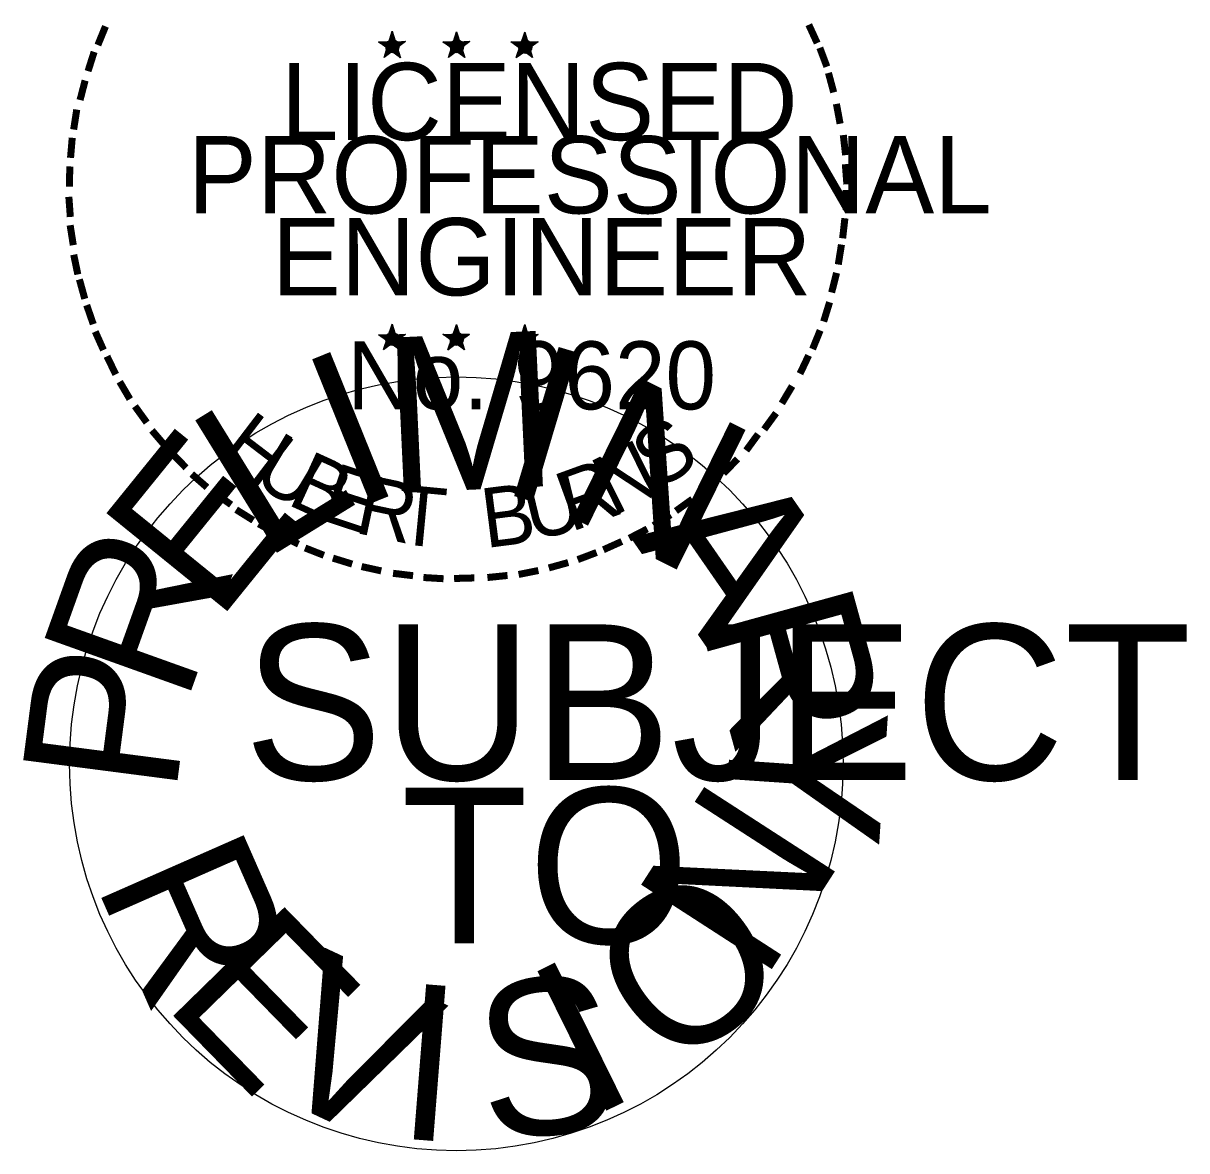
# Model space of a CAD drawing. Extents: x 6028666 to 6031787, y 5366484 to 5368484.
# Drawn here: x 6031338 to 6031786.7, y 5366523.4 to 5366958.2 of the extents above; entities that cross this region are included whole.
import ezdxf

# ---------------------------------------------------------------- set-up
doc = ezdxf.new("R2010")
doc.units = 0
doc.layers.add('Level 49', color=7, linetype='Continuous')
doc.layers.add('R_Border Prelim', color=7, linetype='Continuous')

msp = doc.modelspace()

# ---------------------------------------------------------------- linework, layer by layer
at = {"layer": 'Level 49'}
for p, q in [((6031480.22, 5366955.09), (6031479.51, 5366951.4)), ((6031480.22, 5366955.09), (6031479.52, 5366951.04)), ((6031480.22, 5366955.09), (6031479.88, 5366951.41)), ((6031480.26, 5366949.39), (6031480.22, 5366955.09)), ((6031480.22, 5366955.09), (6031481.17, 5366951.05)), ((6031480.22, 5366955.09), (6031480.98, 5366951.41)), ((6031480.22, 5366955.09), (6031480.43, 5366951.41)), ((6031505.06, 5366954.89), (6031504.35, 5366951.02)), ((6031505.06, 5366954.89), (6031504.35, 5366951.21)), ((6031505.06, 5366954.89), (6031504.53, 5366951.21)), ((6031505.09, 5366949.56), (6031505.06, 5366954.89)), ((6031505.06, 5366954.89), (6031506, 5366951.04)), ((6031505.06, 5366954.89), (6031505.82, 5366951.22)), ((6031505.06, 5366954.89), (6031505.27, 5366951.22)), ((6031531.36, 5366954.71), (6031530.47, 5366951.21)), ((6031531.36, 5366954.71), (6031531.02, 5366951.03)), ((6031531.36, 5366954.71), (6031531.02, 5366951.03)), ((6031531.4, 5366949.19), (6031531.36, 5366954.71)), ((6031531.36, 5366954.71), (6031532.49, 5366951.04)), ((6031531.36, 5366954.71), (6031532.12, 5366951.03)), ((6031531.36, 5366954.71), (6031531.76, 5366951.03)), ((6031474.92, 5366951), (6031480.26, 5366949.39)), ((6031474.92, 5366951), (6031478.78, 5366950.85)), ((6031474.92, 5366951), (6031478.78, 5366950.66)), ((6031474.92, 5366951), (6031478.42, 5366950.11)), ((6031474.92, 5366951), (6031478.42, 5366949.56)), ((6031474.92, 5366951), (6031478.42, 5366949.37)), ((6031474.92, 5366951), (6031478.43, 5366948.82)), ((6031477.17, 5366944.95), (6031480.26, 5366949.39)), ((6031485.4, 5366951.08), (6031480.26, 5366949.39)), ((6031483.42, 5366944.81), (6031480.26, 5366949.39)), ((6031485.4, 5366951.08), (6031480.62, 5366950.68)), ((6031485.4, 5366951.08), (6031481.18, 5366950.31)), ((6031485.4, 5366951.08), (6031481.18, 5366949.94)), ((6031483.42, 5366944.81), (6031481.73, 5366949.4)), ((6031485.4, 5366951.08), (6031481.91, 5366949.95)), ((6031485.4, 5366951.08), (6031482.47, 5366949.59)), ((6031485.4, 5366951.08), (6031482.65, 5366949.4)), ((6031499.75, 5366950.99), (6031505.09, 5366949.56)), ((6031499.75, 5366950.99), (6031503.61, 5366950.84)), ((6031499.75, 5366950.99), (6031503.62, 5366950.47)), ((6031499.75, 5366950.99), (6031503.62, 5366950.28)), ((6031499.75, 5366950.99), (6031503.44, 5366949.55)), ((6031499.75, 5366950.99), (6031503.44, 5366949.36)), ((6031499.75, 5366950.99), (6031503.44, 5366948.81)), ((6031502, 5366944.94), (6031505.09, 5366949.56)), ((6031510.23, 5366951.07), (6031505.09, 5366949.56)), ((6031508.25, 5366944.98), (6031505.09, 5366949.56)), ((6031510.23, 5366951.07), (6031505.64, 5366950.85)), ((6031510.23, 5366951.07), (6031506.01, 5366950.3)), ((6031510.23, 5366951.07), (6031506.01, 5366950.12)), ((6031508.25, 5366944.98), (6031506.02, 5366949.38)), ((6031508.25, 5366944.98), (6031506.57, 5366949.38)), ((6031510.23, 5366951.07), (6031506.75, 5366949.75)), ((6031510.23, 5366951.07), (6031507.3, 5366949.57)), ((6031510.23, 5366951.07), (6031507.49, 5366949.39)), ((6031526.05, 5366950.99), (6031531.4, 5366949.19)), ((6031526.05, 5366950.99), (6031530.29, 5366950.47)), ((6031526.05, 5366950.99), (6031529.92, 5366950.28)), ((6031526.05, 5366950.99), (6031529.92, 5366949.91)), ((6031526.05, 5366950.99), (6031529.74, 5366949.55)), ((6031526.05, 5366950.99), (6031529.75, 5366948.99)), ((6031526.05, 5366950.99), (6031529.75, 5366948.99)), ((6031536.54, 5366951.06), (6031531.4, 5366949.19)), ((6031536.54, 5366951.06), (6031531.94, 5366950.48)), ((6031536.54, 5366951.06), (6031532.5, 5366950.3)), ((6031536.54, 5366951.06), (6031532.5, 5366949.75)), ((6031536.54, 5366951.06), (6031533.24, 5366949.57)), ((6031536.54, 5366951.06), (6031533.42, 5366949.57)), ((6031536.54, 5366951.06), (6031533.98, 5366949.21)), ((6031477.17, 5366944.95), (6031478.42, 5366949.19)), ((6031477.17, 5366944.95), (6031478.8, 5366948.64)), ((6031477.17, 5366944.95), (6031478.98, 5366948.46)), ((6031477.17, 5366944.95), (6031480.27, 5366948.1)), ((6031477.17, 5366944.95), (6031479.54, 5366948.09)), ((6031477.17, 5366944.95), (6031480.27, 5366947.73)), ((6031483.42, 5366944.81), (6031480.27, 5366948.1)), ((6031483.42, 5366944.81), (6031480.27, 5366947.73)), ((6031483.42, 5366944.81), (6031480.64, 5366948.1)), ((6031483.42, 5366944.81), (6031481.18, 5366949.21)), ((6031483.42, 5366944.81), (6031481.19, 5366948.66)), ((6031502, 5366944.94), (6031503.63, 5366949)), ((6031502, 5366944.94), (6031503.63, 5366948.81)), ((6031502, 5366944.94), (6031503.81, 5366948.63)), ((6031502, 5366944.94), (6031505.1, 5366948.09)), ((6031502, 5366944.94), (6031504.37, 5366948.08)), ((6031502, 5366944.94), (6031505.11, 5366947.9)), ((6031508.25, 5366944.98), (6031505.1, 5366948.09)), ((6031508.25, 5366944.98), (6031505.11, 5366947.9)), ((6031508.25, 5366944.98), (6031505.66, 5366948.09)), ((6031508.25, 5366944.98), (6031506.02, 5366948.65)), ((6031528.12, 5366944.94), (6031531.4, 5366949.19)), ((6031528.12, 5366944.94), (6031529.93, 5366948.99)), ((6031528.12, 5366944.94), (6031530.3, 5366948.45)), ((6031528.12, 5366944.94), (6031531.41, 5366948.27)), ((6031528.12, 5366944.94), (6031530.3, 5366948.26)), ((6031528.12, 5366944.94), (6031531.04, 5366948.08)), ((6031528.12, 5366944.94), (6031531.78, 5366947.54)), ((6031534.37, 5366944.98), (6031531.4, 5366949.19)), ((6031534.37, 5366944.98), (6031531.41, 5366948.27)), ((6031534.37, 5366944.98), (6031531.41, 5366947.53)), ((6031534.37, 5366944.98), (6031531.96, 5366948.09)), ((6031534.37, 5366944.98), (6031532.51, 5366949.01)), ((6031534.37, 5366944.98), (6031532.51, 5366948.46)), ((6031534.37, 5366944.98), (6031532.87, 5366949.02)), ((6031480.27, 5366842.15), (6031479.19, 5366838.46)), ((6031480.27, 5366842.15), (6031479.56, 5366838.09)), ((6031480.27, 5366842.15), (6031479.75, 5366838.09)), ((6031480.31, 5366836.44), (6031480.27, 5366842.15)), ((6031480.27, 5366842.15), (6031481.03, 5366838.1)), ((6031480.27, 5366842.15), (6031481.03, 5366838.1)), ((6031480.27, 5366842.15), (6031480.3, 5366838.1)), ((6031505.11, 5366841.95), (6031504.21, 5366838.26)), ((6031505.11, 5366841.95), (6031504.4, 5366838.27)), ((6031505.11, 5366841.95), (6031504.58, 5366838.27)), ((6031505.14, 5366836.62), (6031505.11, 5366841.95)), ((6031505.11, 5366841.95), (6031505.87, 5366838.09)), ((6031505.11, 5366841.95), (6031505.87, 5366838.09)), ((6031505.11, 5366841.95), (6031505.13, 5366838.27)), ((6031531.41, 5366841.95), (6031530.52, 5366838.08)), ((6031531.41, 5366841.95), (6031530.7, 5366838.08)), ((6031531.41, 5366841.95), (6031531.07, 5366838.08)), ((6031531.45, 5366836.25), (6031531.41, 5366841.95)), ((6031531.41, 5366841.95), (6031532.17, 5366838.09)), ((6031531.41, 5366841.95), (6031532.17, 5366838.09)), ((6031531.41, 5366841.95), (6031531.44, 5366838.09)), ((6031474.97, 5366838.06), (6031480.31, 5366836.44)), ((6031474.97, 5366838.06), (6031478.83, 5366837.9)), ((6031474.97, 5366838.06), (6031478.65, 5366837.35)), ((6031474.97, 5366838.06), (6031478.65, 5366837.35)), ((6031474.97, 5366838.06), (6031478.65, 5366836.62)), ((6031474.97, 5366838.06), (6031478.66, 5366836.43)), ((6031474.97, 5366838.06), (6031478.66, 5366836.25)), ((6031485.45, 5366838.13), (6031480.31, 5366836.44)), ((6031485.45, 5366838.13), (6031480.67, 5366837.92)), ((6031485.45, 5366838.13), (6031481.04, 5366837.37)), ((6031485.45, 5366838.13), (6031481.04, 5366837.18)), ((6031485.45, 5366838.13), (6031481.78, 5366837.01)), ((6031485.45, 5366838.13), (6031482.15, 5366836.64)), ((6031485.45, 5366838.13), (6031482.52, 5366836.46)), ((6031499.8, 5366838.23), (6031505.14, 5366836.62)), ((6031499.8, 5366838.23), (6031503.66, 5366837.89)), ((6031499.8, 5366838.23), (6031503.66, 5366837.53)), ((6031499.8, 5366838.23), (6031503.67, 5366837.34)), ((6031499.8, 5366838.23), (6031503.49, 5366836.79)), ((6031499.8, 5366838.23), (6031503.49, 5366836.42)), ((6031499.8, 5366838.23), (6031503.49, 5366836.05)), ((6031510.1, 5366838.12), (6031505.14, 5366836.62)), ((6031510.1, 5366838.12), (6031505.68, 5366838.09)), ((6031510.1, 5366838.12), (6031505.87, 5366837.36)), ((6031510.1, 5366838.12), (6031505.87, 5366837.36)), ((6031510.1, 5366838.12), (6031506.61, 5366836.81)), ((6031510.1, 5366838.12), (6031507.17, 5366836.63)), ((6031510.1, 5366838.12), (6031507.35, 5366836.45)), ((6031526.1, 5366838.05), (6031531.45, 5366836.25)), ((6031526.1, 5366838.05), (6031529.97, 5366837.71)), ((6031526.1, 5366838.05), (6031529.97, 5366837.34)), ((6031526.1, 5366838.05), (6031529.79, 5366836.97)), ((6031526.1, 5366838.05), (6031529.79, 5366836.6)), ((6031526.1, 5366838.05), (6031529.61, 5366836.23)), ((6031526.1, 5366838.05), (6031529.61, 5366835.87)), ((6031536.59, 5366838.12), (6031531.45, 5366836.25)), ((6031536.59, 5366838.12), (6031531.99, 5366837.72)), ((6031536.59, 5366838.12), (6031532.18, 5366837.36)), ((6031536.59, 5366838.12), (6031532.18, 5366836.99)), ((6031536.59, 5366838.12), (6031533.28, 5366836.81)), ((6031536.59, 5366838.12), (6031533.47, 5366836.26)), ((6031536.59, 5366838.12), (6031533.66, 5366836.26)), ((6031476.84, 5366832.37), (6031480.31, 5366836.44)), ((6031476.84, 5366832.37), (6031478.66, 5366836.43)), ((6031476.84, 5366832.37), (6031478.84, 5366835.7)), ((6031476.84, 5366832.37), (6031479.03, 5366835.7)), ((6031476.84, 5366832.37), (6031480.32, 5366835.52)), ((6031476.84, 5366832.37), (6031479.58, 5366835.15)), ((6031476.84, 5366832.37), (6031480.32, 5366834.97)), ((6031483.28, 5366832.05), (6031479.95, 5366834.97)), ((6031483.28, 5366832.05), (6031480.31, 5366836.44)), ((6031483.28, 5366832.05), (6031480.32, 5366835.16)), ((6031483.28, 5366832.05), (6031480.5, 5366835.16)), ((6031483.28, 5366832.05), (6031481.05, 5366836.45)), ((6031483.28, 5366832.05), (6031481.05, 5366835.71)), ((6031483.28, 5366832.05), (6031481.78, 5366836.45)), ((6031501.68, 5366832.18), (6031505.14, 5366836.62)), ((6031501.68, 5366832.18), (6031503.67, 5366836.42)), ((6031501.68, 5366832.18), (6031503.68, 5366835.69)), ((6031501.68, 5366832.18), (6031503.86, 5366835.69)), ((6031501.68, 5366832.18), (6031505.15, 5366835.33)), ((6031501.68, 5366832.18), (6031504.42, 5366835.32)), ((6031501.68, 5366832.18), (6031505.15, 5366834.96)), ((6031508.12, 5366832.22), (6031504.97, 5366834.96)), ((6031508.12, 5366832.22), (6031505.14, 5366836.62)), ((6031508.12, 5366832.22), (6031505.15, 5366835.33)), ((6031508.12, 5366832.22), (6031505.34, 5366835.33)), ((6031508.12, 5366832.22), (6031505.88, 5366836.44)), ((6031508.12, 5366832.22), (6031505.88, 5366835.88)), ((6031508.12, 5366832.22), (6031506.62, 5366836.44)), ((6031528.17, 5366831.99), (6031531.45, 5366836.25)), ((6031528.17, 5366831.99), (6031529.79, 5366836.23)), ((6031528.17, 5366831.99), (6031529.98, 5366835.5)), ((6031528.17, 5366831.99), (6031530.35, 5366835.5)), ((6031528.17, 5366831.99), (6031530.72, 5366835.14)), ((6031528.17, 5366831.99), (6031531.27, 5366835.14)), ((6031528.17, 5366831.99), (6031531.46, 5366834.77)), ((6031534.42, 5366832.04), (6031531.27, 5366835.14)), ((6031534.42, 5366832.04), (6031531.28, 5366834.77)), ((6031534.42, 5366832.04), (6031531.45, 5366836.25)), ((6031534.42, 5366832.04), (6031531.82, 5366835.15)), ((6031534.42, 5366832.04), (6031532.19, 5366835.52)), ((6031534.42, 5366832.04), (6031532.55, 5366836.25)), ((6031534.42, 5366832.04), (6031532.74, 5366836.26))]:
    msp.add_line(p, q, dxfattribs=at)
for points in [[(6031480.22, 5366955.09), (6031483.42, 5366944.81), (6031474.92, 5366951), (6031485.4, 5366951.08), (6031477.17, 5366944.95), (6031480.22, 5366955.09)], [(6031505.06, 5366954.89), (6031508.25, 5366944.98), (6031499.75, 5366950.99), (6031510.23, 5366951.07), (6031502, 5366944.94), (6031505.06, 5366954.89)], [(6031531.36, 5366954.71), (6031534.37, 5366944.98), (6031526.05, 5366950.99), (6031536.54, 5366951.06), (6031528.12, 5366944.94), (6031531.36, 5366954.71)], [(6031480.27, 5366842.15), (6031483.28, 5366832.05), (6031474.97, 5366838.06), (6031485.45, 5366838.13), (6031476.84, 5366832.37), (6031480.27, 5366842.15)], [(6031505.11, 5366841.95), (6031508.12, 5366832.22), (6031499.8, 5366838.23), (6031510.1, 5366838.12), (6031501.68, 5366832.18), (6031505.11, 5366841.95)], [(6031531.41, 5366841.95), (6031534.42, 5366832.04), (6031526.1, 5366838.05), (6031536.59, 5366838.12), (6031528.17, 5366831.99), (6031531.41, 5366841.95)], [(6031600.83, 5366778.78), (6031600.08, 5366781.17), (6031604.46, 5366784.88)], [(6031604.84, 5366783.6), (6031600.45, 5366779.7)], [(6031604.09, 5366785.43), (6031604.84, 5366783.23), (6031600.46, 5366779.33)], [(6031604.84, 5366783.23), (6031600.64, 5366779.52)]]:
    msp.add_lwpolyline(points, dxfattribs=at)
for centre, radius in [((6031480.35, 5366949.29), 2.57), ((6031480.35, 5366949.29), 2.32), ((6031480.35, 5366949.29), 2.15), ((6031480.35, 5366949.29), 1.98), ((6031480.35, 5366949.29), 1.72), ((6031480.35, 5366949.29), 1.6), ((6031480.35, 5366949.29), 1.48), ((6031480.35, 5366949.29), 1.27), ((6031480.35, 5366949.29), 1.11), ((6031480.35, 5366949.29), 0.926), ((6031480.35, 5366949.29), 0.738), ((6031480.35, 5366949.29), 0.551), ((6031480.35, 5366949.29), 0.442), ((6031480.35, 5366949.29), 0.215), ((6031505.23, 5366949.29), 2.57), ((6031505.23, 5366949.29), 2.32), ((6031505.23, 5366949.29), 2.15), ((6031505.23, 5366949.29), 1.98), ((6031505.23, 5366949.29), 1.72), ((6031505.23, 5366949.29), 1.6), ((6031505.23, 5366949.29), 1.48), ((6031505.23, 5366949.29), 1.27), ((6031505.23, 5366949.29), 1.11), ((6031505.23, 5366949.29), 0.926), ((6031505.23, 5366949.29), 0.738), ((6031505.23, 5366949.29), 0.551), ((6031505.23, 5366949.29), 0.442), ((6031505.23, 5366949.29), 0.215), ((6031531.56, 5366949.12), 2.57), ((6031531.56, 5366949.12), 2.32), ((6031531.56, 5366949.12), 2.15), ((6031531.56, 5366949.12), 1.98), ((6031531.56, 5366949.12), 1.72), ((6031531.56, 5366949.12), 1.6), ((6031531.56, 5366949.12), 1.48), ((6031531.56, 5366949.12), 1.27), ((6031531.56, 5366949.12), 1.11), ((6031531.56, 5366949.12), 0.926), ((6031531.56, 5366949.12), 0.738), ((6031531.56, 5366949.12), 0.551), ((6031531.56, 5366949.12), 0.442), ((6031531.56, 5366949.12), 0.215), ((6031480.29, 5366836.44), 2.57), ((6031480.29, 5366836.44), 2.32), ((6031480.29, 5366836.44), 2.15), ((6031480.29, 5366836.44), 1.98), ((6031480.29, 5366836.44), 1.72), ((6031480.29, 5366836.44), 1.6), ((6031480.29, 5366836.44), 1.48), ((6031480.29, 5366836.44), 1.27), ((6031480.29, 5366836.44), 1.11), ((6031480.29, 5366836.44), 0.926), ((6031480.29, 5366836.44), 0.738), ((6031505.17, 5366836.44), 2.57), ((6031505.17, 5366836.44), 2.32), ((6031505.17, 5366836.44), 2.15), ((6031505.17, 5366836.44), 1.98), ((6031505.17, 5366836.44), 1.72), ((6031505.17, 5366836.44), 1.6), ((6031505.17, 5366836.44), 1.48), ((6031505.17, 5366836.44), 1.27), ((6031505.17, 5366836.44), 1.11), ((6031505.17, 5366836.44), 0.926), ((6031505.17, 5366836.44), 0.738), ((6031531.5, 5366836.26), 2.57), ((6031531.5, 5366836.26), 2.32), ((6031531.5, 5366836.26), 2.15), ((6031531.5, 5366836.26), 1.98), ((6031531.5, 5366836.26), 1.72), ((6031531.5, 5366836.26), 1.6), ((6031531.5, 5366836.26), 1.48), ((6031531.5, 5366836.26), 1.27), ((6031531.5, 5366836.26), 1.11), ((6031531.5, 5366836.26), 0.926), ((6031480.29, 5366836.44), 0.551), ((6031480.29, 5366836.44), 0.442), ((6031480.29, 5366836.44), 0.215), ((6031505.17, 5366836.44), 0.551), ((6031505.17, 5366836.44), 0.442), ((6031505.17, 5366836.44), 0.215), ((6031531.5, 5366836.26), 0.738), ((6031531.5, 5366836.26), 0.551), ((6031531.5, 5366836.26), 0.442), ((6031531.5, 5366836.26), 0.215)]:
    msp.add_circle(centre, radius, dxfattribs=at)
at = {"layer": 'R_Border Prelim'}
msp.add_circle((6031504.98, 5366672.6), 149.17, dxfattribs=at)

# ---------------------------------------------------------------- texts
at = {"layer": 'Level 49'}
for s, height, rotation, p in [('-', 23.84, 67.7743, (6031374.71, 5366944.97)), ('-', 23.84, 294.6628, (6031631.98, 5366955.04)), ('-', 23.84, 72.3945, (6031371.28, 5366935.57)), ('-', 23.84, 290.5728, (6031636.08, 5366946.79)), ('-', 23.84, 75.461, (6031368.41, 5366924.88)), ('-', 23.84, 285.1233, (6031639.27, 5366937.98)), ('-', 23.84, 280.5493, (6031642.29, 5366926.78)), ('-', 23.84, 81.2013, (6031366.27, 5366914.38)), ('-', 23.84, 85.1863, (6031365.24, 5366904.07)), ('-', 23.84, 276.5962, (6031644.95, 5366915.4)), ('-', 23.84, 89.0622, (6031364.95, 5366893.59)), ('-', 23.84, 274.3301, (6031645.76, 5366904.55)), ('-', 23.84, 94.1959, (6031365.39, 5366882.74)), ('-', 23.84, 269.9407, (6031646.19, 5366895.35)), ('-', 23.84, 263.5172, (6031645.89, 5366885.42)), ('-', 23.84, 98.9479, (6031366.56, 5366872.63)), ('-', 23.84, 260.9953, (6031644.67, 5366875.66)), ('-', 23.84, 101.7149, (6031368.3, 5366861.79)), ('-', 23.84, 105.4578, (6031370.93, 5366852.98)), ('-', 23.84, 255.7626, (6031643.09, 5366865.53)), ('-', 23.84, 252.8681, (6031640.59, 5366854.66)), ('-', 23.84, 109.0874, (6031374.12, 5366843.8)), ('-', 23.84, 114.0643, (6031377.87, 5366834.63)), ('-', 23.84, 247.8887, (6031637.34, 5366844.52)), ('-', 23.84, 115.7289, (6031382.53, 5366825.46)), ('-', 23.84, 244.6197, (6031633.18, 5366835.3)), ('-', 23.84, 120.4471, (6031387.74, 5366816.67)), ('-', 23.84, 239.0712, (6031627.37, 5366824.22)), ('-', 23.84, 125.8934, (6031393.87, 5366808.44)), ('H', 22.96, 322.6612, (6031412.56, 5366791.27)), ('-', 23.84, 233.8452, (6031621.73, 5366814.43)), ('-', 23.84, 130.7181, (6031400.55, 5366800.2)), ('S', 22.96, 32.7313, (6031582.62, 5366777.74)), ('U', 22.96, 329.0312, (6031425.51, 5366781.43)), ('N', 22.96, 26.3613, (6031565.4, 5366767.87)), ('-', 23.84, 233.8452, (6031614.8, 5366806.29)), ('-', 23.84, 134.2238, (6031408.33, 5366792.16)), ('B', 22.96, 335.4012, (6031439.18, 5366772.88)), ('E', 22.96, 341.7712, (6031451.54, 5366767.08)), ('R', 22.96, 19.9913, (6031549.07, 5366761.87)), ('-', 23.84, 225.7653, (6031607.87, 5366797.6)), ('-', 23.84, 138.9338, (6031415.92, 5366785.23)), ('R', 22.96, 348.1412, (6031465.19, 5366761.84)), ('U', 22.96, 13.6213, (6031533.83, 5366758.45)), ('T', 22.96, 354.5112, (6031481.23, 5366757.54)), ('B', 22.96, 7.2513, (6031516.19, 5366755.76)), ('-', 23.84, 144.6463, (6031424.6, 5366779.22)), ('-', 23.84, 215.7363, (6031591.79, 5366782.95)), ('-', 23.84, 148.0898, (6031432.74, 5366773.57)), ('-', 23.84, 212.2491, (6031583.92, 5366777.2)), ('-', 23.84, 151.5704, (6031441.23, 5366768.85)), ('-', 23.84, 154.6002, (6031449.35, 5366765.04)), ('-', 23.84, 207.3568, (6031575.67, 5366771.99)), ('-', 23.84, 158.5612, (6031458.58, 5366761.06)), ('-', 23.84, 204.2516, (6031566.33, 5366767.32)), ('-', 23.84, 162.7983, (6031468.9, 5366758)), ('-', 23.84, 200.7184, (6031557.16, 5366763.21)), ('-', 23.84, 167.5555, (6031479.4, 5366755.68)), ('-', 23.84, 173.1155, (6031490.82, 5366754.11)), ('-', 23.84, 191.2858, (6031536.23, 5366756.45)), ('-', 23.84, 195.4743, (6031547.07, 5366759.47)), ('-', 23.84, 176.5183, (6031502.04, 5366753.08)), ('-', 23.84, 181.5918, (6031513.08, 5366753.53)), ('-', 23.84, 185.8167, (6031525.21, 5366754.53))]:
    msp.add_text(s, height=height, rotation=rotation, dxfattribs=at).set_placement(p)
for s, height, p in [('LICENSED', 29.805, (6031437.35, 5366913.09)), ('PROFESSIONAL', 29.8052, (6031401.43, 5366884.83)), ('ENGINEER', 29.805, (6031433.84, 5366853.23)), ('No. 9620', 26.227, (6031462.84, 5366809.28))]:
    msp.add_text(s, height=height, dxfattribs=at).set_placement(p)
at = {"layer": 'R_Border Prelim'}
for s, rotation, p in [('M', 2.6943, (6031478.21, 5366776.77)), ('I', 343.3781, (6031520.21, 5366777.97)), ('I', 22.0105, (6031465.01, 5366770.17)), ('N', 333.7199, (6031543.91, 5366770.32)), ('L', 31.6686, (6031430.21, 5366750.52)), ('E', 50.9849, (6031412.51, 5366726.37)), ('A', 304.7456, (6031572.11, 5366759.97)), ('R', 70.3011, (6031400.51, 5366694.72)), ('R', 285.4294, (6031598.21, 5366729.52)), ('P', 82.6089, (6031396.61, 5366659.77)), ('Y', 266.1131, (6031611.71, 5366697.12)), ('N', 57.1378, (6031623.11, 5366587.92)), ('R', 293.7639, (6031365.41, 5366626.92)), ('O', 36.5754, (6031586.81, 5366552.37)), ('E', 314.3262, (6031391.21, 5366580.12)), ('V', 334.8885, (6031428.41, 5366547.57)), ('I', 26.2943, (6031556.21, 5366535.57)), ('S', 5.732, (6031516.01, 5366527.32)), ('I', 355.4508, (6031481.21, 5366528.37))]:
    msp.add_text(s, height=60, rotation=rotation, dxfattribs=at).set_placement(p)
for s, p in [('SUBJECT', (6031423.01, 5366666.37)), ('TO', (6031483.61, 5366603.37))]:
    msp.add_text(s, height=59.999, dxfattribs=at).set_placement(p)

doc.saveas('drawing.dxf')
